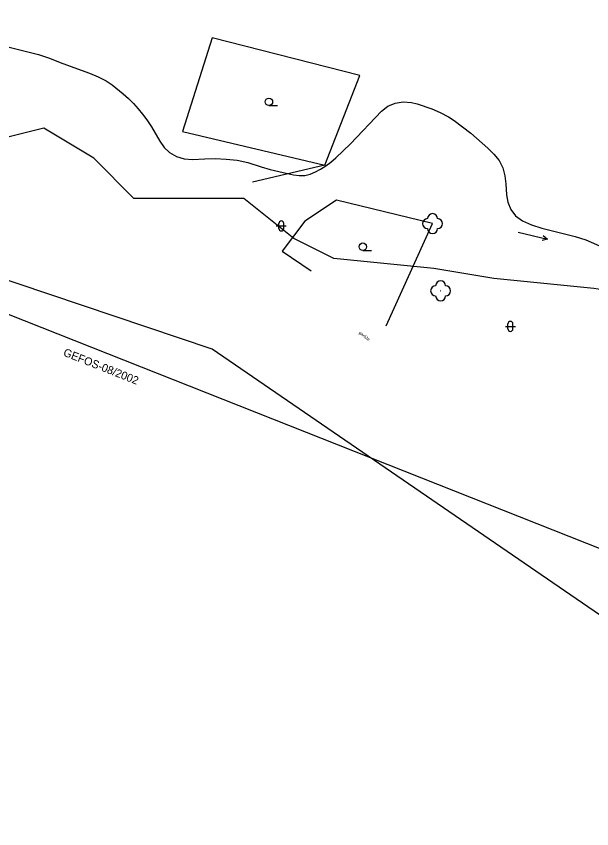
# Model space of a CAD drawing. Extents: x -737422 to -734235, y -1145631 to -1142623.
# Drawn here: x -737062.7 to -737005.2, y -1144839 to -1144757.8 of the extents above; entities that cross this region are included whole.
import ezdxf

# ---------------------------------------------------------------- set-up
doc = ezdxf.new("R2010")
doc.units = 0
for name, color, linetype in [('Vrstva 1', 7, 'Continuous'), ('Vrstva 20', 7, 'Continuous'), ('Vrstva 22', 7, 'Continuous'), ('Vrstva 30', 7, 'Continuous')]:
    doc.layers.add(name, color=color, linetype=linetype)

# ---------------------------------------------------------------- blocks, each defined once
blk = doc.blocks.new('3.040')
at = {"layer": 'Vrstva 1'}
blk.add_line((0, -0.75), (1.75, -0.75), dxfattribs=at)
blk.add_circle((0, 0), 0.75, dxfattribs=at)
blk = doc.blocks.new('3.160')
at = {"layer": 'Vrstva 1'}
for p, q in [((-1, 0), (1, 0)), ((-0.5, -0.5), (-0.5, 0.5)), ((0.5, -0.5), (0.5, 0.5))]:
    blk.add_line(p, q, dxfattribs=at)
for centre, start, end in [((0, 0.5), 0, 180), ((0, -0.5), 180, 360)]:
    blk.add_arc(centre, 0.5, start, end, dxfattribs=at)
blk = doc.blocks.new('3.130')
at = {"layer": 'Vrstva 1'}
blk.add_circle((0, 0), 0.001, dxfattribs=at)
for centre, start, end in [((0, 1), 0, 180), ((-1, 0), 90, 270), ((1, 0), 270, 90), ((0, -1), 180, 360)]:
    blk.add_arc(centre, 1, start, end, dxfattribs=at)
blk = doc.blocks.new('8.021')
at = {"layer": 'Vrstva 1'}
blk.add_line((-3, 0), (3, 0), dxfattribs=at)
blk.add_lwpolyline([(2, 0.5), (3, 0), (2, -0.5)], dxfattribs=at)

msp = doc.modelspace()

# ---------------------------------------------------------------- linework, layer by layer
at = {"layer": 'Vrstva 1'}
for points in [[(-737063.717, -1144760.812), (-737060.529, -1144761.635), (-737059.515, -1144761.96), (-737058.08, -1144762.532), (-737055.413, -1144763.483), (-737054.559, -1144763.835), (-737053.767, -1144764.249), (-737053.166, -1144764.652)], [(-737053.166, -1144764.652), (-737052.047, -1144765.538), (-737051.522, -1144766.011), (-737051.037, -1144766.523), (-737050.577, -1144767.054), (-737050.125, -1144767.589), (-737049.698, -1144768.141), (-737049.242, -1144768.846), (-737048.404, -1144770.269), (-737047.952, -1144770.902), (-737047.428, -1144771.421), (-737046.732, -1144771.819), (-737045.953, -1144772.046), (-737045.139, -1144772.124), (-737043.89, -1144772.057), (-737042.855, -1144772.029), (-737041.759, -1144772.072), (-737040.653, -1144772.199), (-737039.588, -1144772.423), (-737038.262, -1144772.848), (-737037.366, -1144773.105), (-737035.627, -1144773.522), (-737035.039, -1144773.651), (-737034.473, -1144773.727), (-737033.908, -1144773.709), (-737033.357, -1144773.588), (-737032.834, -1144773.366), (-737032.321, -1144773.075), (-737031.8, -1144772.744), (-737031.286, -1144772.368), (-737030.794, -1144771.94), (-737029.318, -1144770.545), (-737026.249, -1144767.276), (-737025.603, -1144766.783), (-737024.863, -1144766.475), (-737024.063, -1144766.352), (-737023.252, -1144766.405), (-737022.657, -1144766.552), (-737021.216, -1144767.063), (-737020.361, -1144767.418), (-737019.537, -1144767.849), (-737018.961, -1144768.232), (-737017.301, -1144769.486), (-737015.62, -1144770.985), (-737014.996, -1144771.579), (-737014.479, -1144772.227), (-737014.121, -1144772.965), (-737013.903, -1144773.754), (-737013.797, -1144774.538), (-737013.733, -1144775.651)], [(-737013.733, -1144775.651), (-737013.592, -1144776.397), (-737013.31, -1144777.114), (-737012.85, -1144777.74), (-737012.133, -1144778.263), (-737011.233, -1144778.659), (-737010.209, -1144778.975), (-737006.872, -1144779.808), (-737005.81, -1144780.163), (-737002.557, -1144781.579)]]:
    msp.add_lwpolyline(points, dxfattribs=at)
at = {"layer": 'Vrstva 20'}
for points in [[(-737031.9, -1144772.69), (-737028.41, -1144763.71), (-737043.17, -1144759.96), (-737046.12, -1144769.31), (-737031.9, -1144772.69)], [(-737031.9, -1144772.69), (-737039.14, -1144774.39)], [(-737030.73, -1144776.19), (-737033.9, -1144778.29), (-737036.17, -1144781.27), (-737033.25, -1144783.26)], [(-737021.13, -1144778.53), (-737030.73, -1144776.19)], [(-736920.4, -1144878.06), (-736972.09, -1144839.84), (-737043.15, -1144791.09), (-737078.91, -1144779.06), (-737081, -1144796.97)], [(-737025.76, -1144788.75), (-737021.13, -1144778.53)]]:
    msp.add_lwpolyline(points, dxfattribs=at)
at = {"layer": 'Vrstva 30'}
for points in [[(-737312.25, -1144551.23), (-737277.23, -1144584.21), (-737291.65, -1144635.73), (-737173.72, -1144683.14), (-737162.39, -1144723.33), (-737091.6, -1144776.48), (-737004.14, -1144811.1), (-736946.11, -1144825.41), (-736889.46, -1144827.57), (-736808.94, -1144821.316)], [(-736944, -1144799), (-736957, -1144797), (-736973, -1144793), (-736992, -1144787), (-737005, -1144785), (-737015, -1144784), (-737021, -1144783), (-737031, -1144782), (-737035, -1144780), (-737040, -1144776), (-737046, -1144776), (-737051, -1144776), (-737055, -1144772), (-737060, -1144769), (-737064, -1144770)]]:
    msp.add_lwpolyline(points, dxfattribs=at)

# ---------------------------------------------------------------- block references
at = {"layer": 'Vrstva 20', "xscale": 0.5, "yscale": 0.5}
for name, p in [('3.040', (-737037.49, -1144766.35)), ('3.130', (-737021.13, -1144778.53)), ('3.160', (-737036.25, -1144778.76)), ('3.040', (-737028.1, -1144780.84)), ('3.130', (-737020.32, -1144785.25)), ('3.160', (-737013.35, -1144788.8))]:
    msp.add_blockref(name, p, dxfattribs=at)
at = {"layer": 'Vrstva 20', "xscale": 0.5000000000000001, "yscale": 0.5, "rotation": -13.64992279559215}
msp.add_blockref('8.021', (-737011.1, -1144779.73), dxfattribs=at)

# ---------------------------------------------------------------- texts
at = {"layer": 'Vrstva 22'}
msp.add_text('garáže', height=0.3, rotation=321.462, dxfattribs=at).set_placement((-737028.52, -1144789.49))
at = {"layer": 'Vrstva 30'}
msp.add_text('GEFOS-08/2002', height=0.8, rotation=338.405, dxfattribs=at).set_placement((-737058.12, -1144791.71))

doc.saveas('drawing.dxf')
